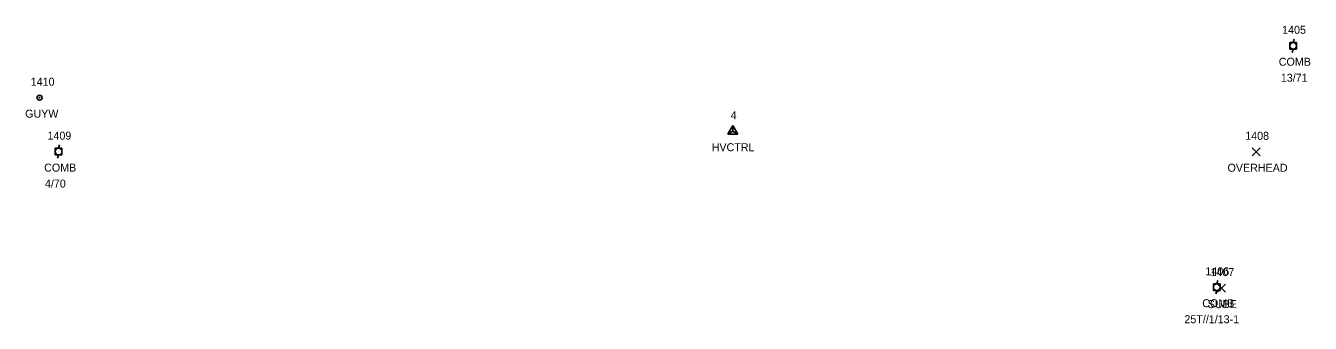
# Model space of a CAD drawing. Extents: x 1514253 to 1516033, y 782541 to 785002.
# Drawn here: x 1514683.1 to 1515004.2, y 782636.2 to 782710.8 of the extents above; entities that cross this region are included whole.
import ezdxf

# ---------------------------------------------------------------- set-up
doc = ezdxf.new("R2010")
doc.units = 0
for name, color, linetype in [('C_A', 7, 'Continuous'), ('C_I', 7, 'Continuous'), ('CPSM', 7, 'Continuous'), ('U_A', 7, 'Continuous'), ('U_C', 7, 'Continuous'), ('U_I', 7, 'Continuous'), ('U_TIC', 7, 'Continuous'), ('UP', 7, 'Continuous'), ('UPGW', 7, 'Continuous')]:
    doc.layers.add(name, color=color, linetype=linetype)

msp = doc.modelspace()

# ---------------------------------------------------------------- linework, layer by layer
at = {"layer": 'CPSM'}
for p, q in [((1514858.65, 782683.61), (1514859.9, 782685.78)), ((1514861.15, 782683.61), (1514859.9, 782685.78)), ((1514859.9, 782684.33), (1514859.9, 782685.78)), ((1514858.65, 782683.61), (1514859.9, 782684.33)), ((1514858.65, 782683.61), (1514861.15, 782683.61)), ((1514859.9, 782684.33), (1514859.9, 782684.33)), ((1514859.9, 782684.33), (1514861.15, 782683.61))]:
    msp.add_line(p, q, dxfattribs=at)
at = {"layer": 'U_TIC'}
for points in [[(1514989.74, 782678.19), (1514991.74, 782680.19)], [(1514991.74, 782678.19), (1514989.74, 782680.19)], [(1514981.05, 782644.06), (1514983.05, 782646.06)], [(1514983.05, 782644.06), (1514981.05, 782646.06)]]:
    msp.add_lwpolyline(points, dxfattribs=at)
at = {"layer": 'UP'}
for p, q in [((1514999.14, 782704.9), (1514999.14, 782706.57)), ((1514999.14, 782706.57), (1515000.81, 782706.57)), ((1515000.81, 782704.9), (1514999.14, 782704.9)), ((1514999.72, 782704.07), (1514999.97, 782704.9)), ((1515000.22, 782707.4), (1514999.97, 782706.57)), ((1514999.97, 782705.73), (1514999.97, 782705.73)), ((1515000.81, 782706.57), (1515000.81, 782704.9)), ((1514690.52, 782678.39), (1514690.52, 782680.06)), ((1514690.52, 782680.06), (1514692.18, 782680.06)), ((1514691.6, 782680.89), (1514691.35, 782680.06)), ((1514691.35, 782679.23), (1514691.35, 782679.23)), ((1514692.18, 782680.06), (1514692.18, 782678.39)), ((1514692.18, 782678.39), (1514690.52, 782678.39)), ((1514691.1, 782677.56), (1514691.35, 782678.39)), ((1514981.1, 782646.94), (1514980.85, 782646.11)), ((1514980.01, 782644.44), (1514980.01, 782646.11)), ((1514980.01, 782646.11), (1514981.68, 782646.11)), ((1514981.68, 782644.44), (1514980.01, 782644.44)), ((1514980.6, 782643.61), (1514980.85, 782644.44)), ((1514980.85, 782645.28), (1514980.85, 782645.28)), ((1514981.68, 782646.11), (1514981.68, 782644.44))]:
    msp.add_line(p, q, dxfattribs=at)
for centre in [(1514999.97, 782705.73), (1514691.35, 782679.23), (1514980.85, 782645.28)]:
    msp.add_circle(centre, 0.833, dxfattribs=at)
at = {"layer": 'UPGW'}
for radius in [0.625, 0.0833]:
    msp.add_circle((1514686.59, 782692.73), radius, dxfattribs=at)

# ---------------------------------------------------------------- texts
at = {"layer": 'C_A'}
msp.add_text('HVCTRL', height=2, dxfattribs=at).set_placement((1514854.6, 782679.33))
at = {"layer": 'C_I'}
msp.add_text('4', height=2, dxfattribs=at).set_placement((1514859.34, 782687.33))
at = {"layer": 'U_A'}
for s, p in [('COMB', (1514996.36, 782700.73)), ('GUYW', (1514682.98, 782687.73)), ('COMB', (1514687.74, 782674.23)), ('OVERHEAD', (1514983.55, 782674.19)), ('COMB', (1514977.23, 782640.28)), ('SUBE', (1514978.59, 782640.06))]:
    msp.add_text(s, height=2, dxfattribs=at).set_placement(p)
at = {"layer": 'U_C'}
for s, p in [('13/71', (1514996.87, 782696.73)), ('4/70', (1514687.93, 782670.23)), ('25T//1/13-1', (1514972.77, 782636.28))]:
    msp.add_text(s, height=2, dxfattribs=at).set_placement(p)
at = {"layer": 'U_I'}
for s, p in [('1405', (1514997.2, 782708.73)), ('1410', (1514684.38, 782695.73)), ('1409', (1514688.57, 782682.23)), ('1408', (1514987.97, 782682.19)), ('1406', (1514978.02, 782648.28)), ('1407', (1514979.28, 782648.06))]:
    msp.add_text(s, height=2, dxfattribs=at).set_placement(p)

doc.saveas('drawing.dxf')
